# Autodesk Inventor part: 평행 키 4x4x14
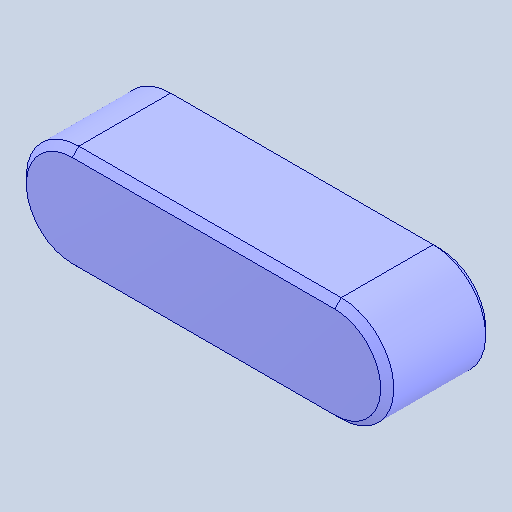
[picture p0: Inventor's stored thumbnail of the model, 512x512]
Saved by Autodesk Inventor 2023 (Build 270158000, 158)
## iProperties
Created: 2026-06
Part Number: 평행 키 4x4x14
Material: 강철, 연강
Description: 키 및 해당 키홈
Document SubType Name: Modeling
Designer: home
Density: 7.85 g/cm^3
Appearance: 기본값
Author: jhkim
Sending System: Autodesk Inventor 2027
Preprocessor: ST-DEVELOPER v20.1
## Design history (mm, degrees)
feature "Solid1"
node "솔리드1"
